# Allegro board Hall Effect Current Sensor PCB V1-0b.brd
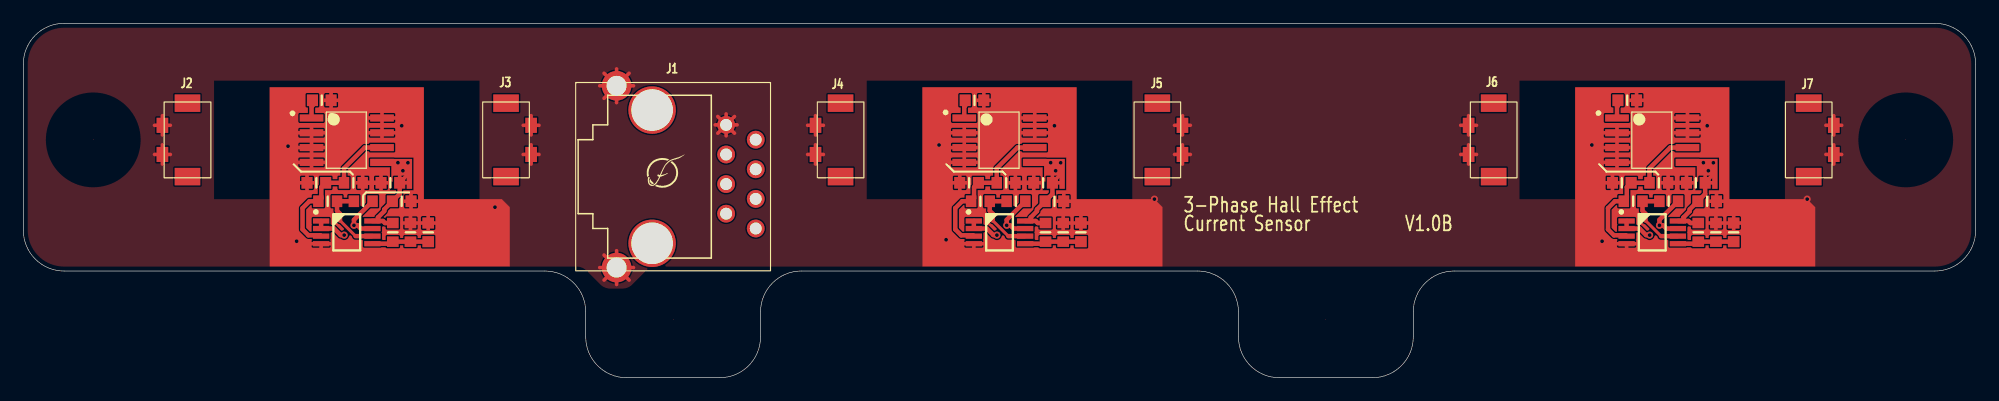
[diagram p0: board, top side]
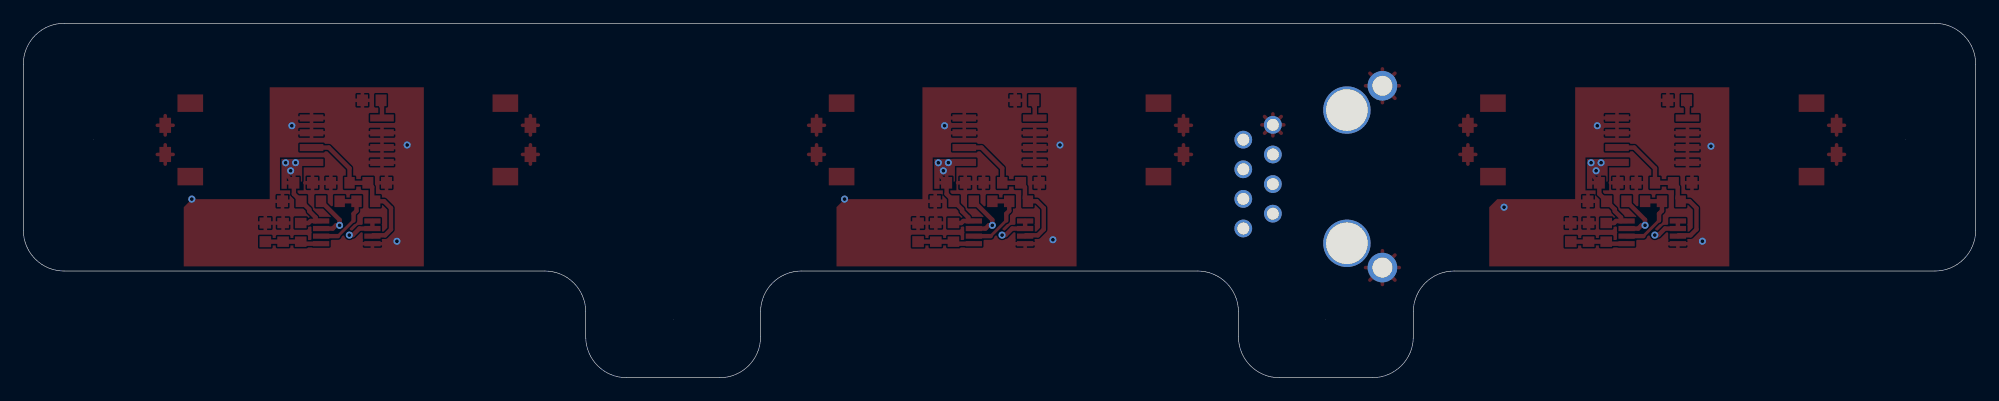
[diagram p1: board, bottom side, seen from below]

Outline 167.5 x 30.4 mm; copper layers: TOP, LAYER_2, LAYER_3, BOTTOM. Coordinates in mm from the lower left corner of the outline.
Outline path: 0,26.9 arc(1.03,29.37) 3.5,30.4 164,30.4 arc(166.47,29.37) 167.5,26.9 167.5,12.65 arc(166.47,10.18) 164,9.15 122.75,9.15 arc(120.28,8.12) 119.25,5.65 119.25,3.5 arc(118.22,1.03) 115.75,0 107.75,0 arc(105.28,1.03) 104.25,3.5 104.25,5.65 arc(103.22,8.12) 100.75,9.15 66.75,9.15 arc(64.28,8.12) 63.25,5.65 63.25,3.5 arc(62.22,1.03) 59.75,0 51.75,0 arc(49.28,1.03) 48.25,3.5 48.25,5.65 arc(47.22,8.12) 44.75,9.15 3.5,9.15 arc(1.03,10.18) 0,12.65 0,26.9

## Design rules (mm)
constraint set DEFAULT: min track width 0.127, pair gap 0.178
net group OUTPUT_A: nets OUTPUT_A_N OUTPUT_A_P
net group OUTPUT_B: nets OUTPUT_B_N OUTPUT_B_P
net group OUTPUT_C: nets OUTPUT_C_N OUTPUT_C_P

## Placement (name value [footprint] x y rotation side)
C1  0.047uF  [CAPC1608X90N]  25.61 23.8 0 top
C2  0.1uF  [CAPC1608X87N]  31.49 16.72 180 top
C3  10000pF  [CAPC1608X90N]  25.14 16.72 180 top
C4  0.047uF  [CAPC1608X90N]  81.61 23.8 0 top
C5  0.1uF  [CAPC1608X87N]  87.49 16.72 180 top
C6  10000pF  [CAPC1608X90N]  81.14 16.72 180 top
C7  0.047uF  [CAPC1608X90N]  137.61 23.8 0 top
C8  0.1uF  [CAPC1608X87N]  143.49 16.72 180 top
C9  10000pF  [CAPC1608X90N]  137.14 16.72 180 top
C10  0.1uF  [CAPC1608X87N]  34.74 12.47 90 top
C11  0.1uF  [CAPC1608X87N]  90.74 12.47 90 top
C12  0.1uF  [CAPC1608X87N]  146.74 12.47 90 top
CB19  0.1uF  [CAPC1608X87N]  32.46 15.14 0 top
CB20  0.1uF  [CAPC1608X87N]  88.46 15.14 0 top
CB21  0.1uF  [CAPC1608X87N]  144.46 15.14 0 top
J1  A-2014-2S-4-N-R  [RJ45_VERT_SHIELD_CON]  60.3 21.69 90 top
J2  CON2  [AVX_9155_MOBO_2PIN]  14.08 20.4 90 top
J3  CON2  [AVX_9155_MOBO_2PIN]  41.42 20.4 270 top
J4  CON2  [AVX_9155_MOBO_2PIN]  70.11 20.4 90 top
J5  CON2  [AVX_9155_MOBO_2PIN]  97.3 20.4 270 top
J6  CON2  [AVX_9155_MOBO_2PIN]  126.14 20.4 90 top
J7  CON2  [AVX_9155_MOBO_2PIN]  153.18 20.4 270 top
NOREF  -  []  100.73 15.82 0 top
NOREF#2  -  []  16.74 24.91 0 top
NOREF#3  -  []  53.48 16.3 0 top
NOREF#4  -  [unnamed#2]  55.75 5 0 top
NOREF#5  -  [unnamed#2]  111.75 5 0 top
NOREF#6  -  [unnamed#2]  6 20.4 0 top
NOREF#7  -  []  16.74 15.7 90 top
NOREF#8  -  [unnamed#2]  161.5 20.4 0 top
NOREF#9  -  []  0 19.77 0 top
NOREF#10  -  []  55.75 0 90 top
R1  10k  [RESC1608X55N]  28.31 16.72 180 top
R4  10k  [RESC1608X55N]  84.31 16.72 180 top
R6  10k  [RESC1608X55N]  140.31 16.72 180 top
R7  10k  [RESC1608X55N]  29.16 15.14 0 top
R8  10k  [RESC1608X55N]  26.11 15.14 0 top
R9  10k  [RESC1608X55N]  85.16 15.14 0 top
R10  10k  [RESC1608X55N]  82.11 15.14 0 top
R11  10k  [RESC1608X55N]  141.16 15.14 0 top
R12  10k  [RESC1608X55N]  138.11 15.14 0 top
R13  10k  [RESC1608X55N]  33.21 12.47 90 top
R14  10k  [RESC1608X55N]  31.7 12.47 270 top
R15  10k  [RESC1608X55N]  87.7 12.47 270 top
R16  10k  [RESC1608X55N]  89.21 12.47 90 top
R17  10k  [RESC1608X55N]  143.7 12.47 270 top
R18  10k  [RESC1608X55N]  145.21 12.47 90 top
U1  MLX91208LDC-CAH-000-TU  [SOIC_8]  24.73 22.28 0 top
U2  MLX91208LDC-CAH-000-TU  [SOIC_8]  80.73 22.28 0 top
U3  MLX91208LDC-CAH-000-TU  [SOIC_8]  136.73 22.28 0 top
U4  AD8616ARMZ-REEL  [MSOP8_0_65X4_40P_H1_10]  27.75 12.47 0 top
U5  AD8616ARMZ-REEL  [MSOP8_0_65X4_40P_H1_10]  83.75 12.47 0 top
U6  AD8616ARMZ-REEL  [MSOP8_0_65X4_40P_H1_10]  139.75 12.47 0 top

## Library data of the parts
C1-C12 CB19-CB21 = CAP
J1 = ModularJack8P8C-shielded
J2-J7 = CON2
R1 R4 R6 = RES_0
R7-R18 = R
U1-U3 = MLX91208
U4-U6 = OPAMP_2X_8P

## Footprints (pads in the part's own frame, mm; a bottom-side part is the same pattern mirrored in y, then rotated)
AVX_9155_MOBO_2PIN
  rect 1.5x2.2 smd: (-3.15,0) (3.15,0)
  rect 1.3x1 smd: 1(-1.25,2.15) 2(1.25,2.15)
CAPC1608X87N
  rect 0.95x1 smd: 1(-0.8,0) 2(0.8,0)
CAPC1608X90N
  rect 0.95x1 smd: 1(-0.8,0) 2(0.8,0)
MSOP8_0_65X4_40P_H1_10
  rect 1.4x0.45 smd: 1(-2.2,0.975) 2(-2.2,0.325) 3(-2.2,-0.325) 4(-2.2,-0.975) 5(2.2,-0.975) 6(2.2,-0.325) 7(2.2,0.325) 8(2.2,0.975)
RESC1608X55N
  rect 0.9x1 smd: 1(-0.8,0) 2(0.8,0)
RJ45_VERT_SHIELD_CON
  round 4.064 hole 3.556: (-10.16,6.35) (1.27,6.35)
  round 1.524 hole 1.016: 1(0,0) 2(-1.27,-2.54) 3(-2.54,0) 4(-3.81,-2.54) 5(-5.08,0) 6(-6.35,-2.54) 7(-7.62,0) 8(-8.89,-2.54)
  round 2.54 hole 1.702: S1(3.353,9.398) S2(-12.243,9.398)
SOIC_8
  rect 2.032x0.61 smd: 1(0,0) 2(0,-1.27) 3(0,-2.54) 4(0,-3.81) 5(6.045,-3.81) 6(6.045,-2.54) 7(6.045,-1.27) 8(6.045,0)
unnamed#2
  round 0.025 hole 4.496 unplated: (0,0)

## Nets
+2V5REF_A: C10.1 R13.1 R14.2 U4.5
+2V5REF_B: C11.1 R15.2 R16.1 U5.5
+2V5REF_C: C12.1 R17.2 R18.1 U6.5
+5V: C2.1 C5.1 C8.1 CB19.1 CB20.1 CB21.1 J1.2 R14.1 R15.1 R17.1 U1.5 U2.5 U3.5 U4.8 U5.8 U6.8
0: C1.2 C2.2 C3.2 C4.2 C5.2 C6.2 C7.2 C8.2 C9.2 C10.2 C11.2 C12.2 CB19.2 CB20.2 CB21.2 J1.1 J1.S1 J1.S2(SHIELD2) J2.1 J2.2 J3.1 J3.2 J4.1 J4.2 J5.1 J5.2 J6.1 J6.2 J7.1 J7.2 R1.1 R4.1 R6.1 R13.2 R16.2 R18.2 U1.2 U1.3(VSS) U1.4 U1.7 U1.8 U2.2 U2.3(VSS) U2.4 U2.7 U2.8 U3.2 U3.3(VSS) U3.4 U3.7 U3.8 U4.4 U5.4 U6.4
OUTPUT_A: C3.1 R1.2 R8.1 U1.6 U4.3
OUTPUT_A_N: J1.3 R7.2 U4.7(OUT2)
OUTPUT_A_P: J1.6 U4.1 U4.2
OUTPUT_B: C6.1 R4.2 R10.1 U2.6 U5.3
OUTPUT_B_N: J1.5 R9.2 U5.7(OUT2)
OUTPUT_B_P: J1.4 U5.1 U5.2
OUTPUT_C: C9.1 R6.2 R12.1 U3.6 U6.3
OUTPUT_C_N: J1.7 R11.2 U6.7(OUT2)
OUTPUT_C_P: J1.8 U6.1 U6.2
N4844729: C1.1 U1.1
N4845886: C4.1 U2.1
N4846468: C7.1 U3.1
N4848257: R7.1 R8.2 U4.6
N4851782: R9.1 R10.2 U5.6
N4852376: R11.1 R12.2 U6.6

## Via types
v1: diameter 0.61, hole 0.33, TOP to BOTTOM, 27 vias

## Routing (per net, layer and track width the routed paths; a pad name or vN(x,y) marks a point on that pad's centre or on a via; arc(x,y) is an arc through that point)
+2V5REF_A: length 4.9
  TOP w0.381: U4.5 31.53,11.49 R14.2 R13.1 C10.1
+2V5REF_B: length 4.9
  TOP w0.381: C11.1 R16.1 R15.2 87.53,11.49 U5.5
+2V5REF_C: length 4.9
  TOP w0.381: U6.5 143.53,11.49 R17.2 R18.1 C12.1
+5V: length 31.3
  TOP w0.305: C5.1 88.93,17.4 ; C5.1 88.94,16.72 ; C5.1 88.29,17.4 ; C2.1 32.29,17.4 ; C2.1 32.94,16.72 ; C2.1 32.93,17.4 ; C8.1 144.93,17.4 ; C8.1 144.29,17.4 ; C8.1 144.94,16.72
  TOP w0.381: R15.1 87.03,13.27 86.85,13.44 86.43,13.44 ; C5.1 88.29,15.76 CB20.1 86.96,14.44 86.96,14.28 86.43,13.74 86.43,13.44 ; 86.43,13.44 U5.8 ; 30.43,13.44 30.85,13.44 31.03,13.27 R14.1 ; 30.43,13.44 30.43,13.74 30.96,14.28 30.96,14.44 CB19.1 32.29,15.76 C2.1 ; 30.43,13.44 U4.8 ; 142.43,13.44 142.85,13.44 143.03,13.27 R17.1 ; 142.43,13.44 142.43,13.74 142.96,14.28 142.96,14.44 CB21.1 144.29,15.76 C8.1 ; 142.43,13.44 U6.8
  LAYER_2 w0.305: J1.2 63.78,20.42 ; J1.2 62.12,19.7 ; J1.2 62.84,21.36 ; J1.2 61.9,20.42 ; J1.2 63.55,21.13 ; J1.2 63.55,19.7 ; J1.2 62.12,21.13
  vias: v1(32.14,18.44) v1(32.57,17.75) v1(33,18.44) v1(88.14,18.44) v1(88.57,17.75) v1(89,18.44) v1(144.14,18.44) v1(144.57,17.75) v1(145,18.44)
0: length 199
  TOP w0.305: 137.55,11.09 U6.4 ; U6.4 138.43,11.49 ; U6.4 136.67,11.49 ; 30.77,22.28 30.77,22.76 ; 30.77,22.28 31.97,22.28 ; 30.77,22.28 29.58,22.28 ; 30.77,22.28 30.77,21.8 ; 145.26,14.46 CB21.2 ; CB21.2 145.26,15.81 ; CB21.2 145.92,15.14 ; CB21.2 144.61,15.14 ; 60.3,20.75 J1.1 ; J1.1 61.24,21.69 ; J1.1 59.58,20.97 ; J1.1 59.36,21.69 ; J1.1 61.01,20.97 ; J1.1 60.3,22.63 ; J1.1 59.58,22.4 ; J1.1 61.01,22.4 ; 98.77,21.65 J5.1 ; J5.1 99.45,20.82 ; J5.1 99.45,22.48 ; J5.1 100.12,21.65 ; R13.2 33.21,13.9 ; R13.2 32.54,13.27 ; R13.2 33.21,12.64 ; R13.2 33.89,13.27 ; 80.73,20.53 U2.2 ; U2.2 79.53,21.01 ; U2.2 81.92,21.01 ; U2.2 80.73,21.49 ; 123.99,20.82 J6.2 ; J6.2 124.67,21.65 ; J6.2 123.32,21.65 ; J6.2 123.99,22.48 ; J2.2 12.61,21.65 ; J2.2 11.93,20.82 ; J2.2 11.26,21.65 ; J2.2 11.93,22.48 ; 30.77,21.01 31.97,21.01 ; 30.77,21.01 30.77,21.49 ; 30.77,21.01 29.58,21.01 ; 30.77,21.01 30.77,20.53 ; 98.77,19.15 J5.2 ; J5.2 99.45,18.32 ; J5.2 99.45,19.98 ; J5.2 100.12,19.15 ; 25.55,11.09 U4.4 ; U4.4 24.67,11.49 ; U4.4 26.43,11.49 ; U5.4 82.43,11.49 ; U5.4 80.67,11.49 ; U5.4 81.55,11.09 ; U2.3 81.92,19.74 ; U2.3 80.73,19.26 ; U2.3 79.53,19.74 ; U2.3 80.73,20.22 ; 85.58,21.01 U2.7 ; U2.7 86.77,21.49 ; U2.7 87.97,21.01 ; U2.7 86.77,20.53 ; J3.1 43.57,22.48 ; J3.1 43.57,20.82 ; J3.1 44.24,21.65 ; J3.1 42.89,21.65 ; U3.2 137.92,21.01 ; U3.2 136.73,20.53 ; U3.2 136.73,21.49 ; U3.2 135.53,21.01 ; 79.69,16.72 C6.2 ; C6.2 80.34,16.04 ; C6.2 80.34,17.4 ; C6.2 80.99,16.72 ; 155.33,20.82 J7.1 ; J7.1 154.65,21.65 ; J7.1 156,21.65 ; J7.1 155.33,22.48 ; R16.2 89.21,13.9 ; R16.2 89.21,12.64 ; R16.2 89.89,13.27 ; R16.2 88.54,13.27 ; 80.73,17.99 U2.4 ; U2.4 79.53,18.47 ; U2.4 81.92,18.47 ; U2.4 80.73,18.95 ; C7.2 139.06,23.8 ; C7.2 137.75,23.8 ; C7.2 138.41,24.47 ; C7.2 138.41,23.12 ; 85.58,22.28 U2.8 ; U2.8 86.77,22.76 ; U2.8 86.77,21.8 ; U2.8 87.97,22.28 ; R18.2 145.89,13.27 ; R18.2 145.21,13.9 ; R18.2 144.54,13.27 ; R18.2 145.21,12.64 ; C12.2 147.41,13.27 ; C12.2 146.74,13.92 ; C12.2 146.06,13.27 ; C12.2 146.74,12.62 ; J1.S1 51.97,26.12 ; J1.S1 50.9,26.49 ; J1.S1 49.82,23.97 ; J1.S1 49.82,26.12 ; J1.S1 50.9,23.59 ; J1.S1 49.45,25.04 ; J1.S1 52.35,25.04 ; J1.S2 51.97,8.37 ; J1.S2 52.35,9.45 ; J1.S2 50.9,8 ; J1.S2 49.82,8.37 ; J1.S2 50.9,10.89 ; J1.S2 49.45,9.45 ; J1.S2 49.82,10.52 ; 43.57,18.32 J3.2 ; J3.2 44.24,19.15 ; J3.2 43.57,19.98 ; J3.2 42.89,19.15 ; 135.69,16.72 C9.2 ; C9.2 136.34,16.04 ; C9.2 136.34,17.4 ; C9.2 136.99,16.72 ; 82.41,23.12 C4.2 ; C4.2 81.75,23.8 ; C4.2 83.06,23.8 ; C4.2 82.41,24.47 ; 90.74,12.62 C11.2 ; C11.2 91.41,13.27 ; C11.2 90.06,13.27 ; C11.2 90.74,13.92 ; J6.1 123.99,19.98 ; J6.1 123.99,18.32 ; J6.1 123.32,19.15 ; J6.1 124.67,19.15 ; C8.2 142.69,17.4 ; C8.2 143.34,16.72 ; C8.2 142.69,16.04 ; 142.77,21.8 U3.8 ; U3.8 142.77,22.76 ; U3.8 143.97,22.28 ; U3.8 141.58,22.28 ; 84.49,16.72 R4.1 ; R4.1 85.11,17.4 ; R4.1 85.11,16.04 ; 24.73,19.26 U1.3 ; U1.3 25.92,19.74 ; U1.3 23.53,19.74 ; U1.3 24.73,20.22 ; C3.2 24.34,17.4 ; C3.2 24.34,16.04 ; C3.2 23.69,16.72 ; C3.2 24.99,16.72 ; 24.73,17.99 U1.4 ; U1.4 23.53,18.47 ; U1.4 24.73,18.95 ; U1.4 25.92,18.47 ; C10.2 35.41,13.27 ; C10.2 34.06,13.27 ; C10.2 34.74,13.92 ; C10.2 34.74,12.62 ; 67.29,19.15 J4.1 ; J4.1 67.96,19.98 ; J4.1 67.96,18.32 ; J4.1 68.64,19.15 ; 30.69,16.04 C2.2 ; C2.2 31.34,16.72 ; C2.2 30.69,17.4 ; 28.49,16.72 R1.1 ; R1.1 29.11,16.04 ; R1.1 29.11,17.4 ; 86.69,16.04 C5.2 ; C5.2 87.34,16.72 ; C5.2 86.69,17.4 ; U3.3 137.92,19.74 ; U3.3 136.73,19.26 ; U3.3 135.53,19.74 ; U3.3 136.73,20.22 ; J7.2 155.33,19.98 ; J7.2 156,19.15 ; J7.2 155.33,18.32 ; J7.2 154.65,19.15 ; 26.41,23.12 C1.2 ; C1.2 25.75,23.8 ; C1.2 27.06,23.8 ; C1.2 26.41,24.47 ; 67.96,20.82 J4.2 ; J4.2 68.64,21.65 ; J4.2 67.96,22.48 ; J4.2 67.29,21.65 ; U3.7 142.77,21.49 ; U3.7 142.77,20.53 ; U3.7 143.97,21.01 ; U3.7 141.58,21.01 ; J2.1 12.61,19.15 ; J2.1 11.26,19.15 ; J2.1 11.93,18.32 ; J2.1 11.93,19.98 ; R6.1 141.11,17.4 ; R6.1 141.11,16.04 ; R6.1 140.49,16.72 ; CB20.2 89.26,15.81 ; CB20.2 89.92,15.14 ; CB20.2 89.26,14.46 ; CB20.2 88.61,15.14 ; 32.61,15.14 CB19.2 ; CB19.2 33.26,15.81 ; CB19.2 33.92,15.14 ; CB19.2 33.26,14.46 ; 136.73,17.99 U3.4 ; U3.4 135.53,18.47 ; U3.4 137.92,18.47 ; U3.4 136.73,18.95 ; U1.2 25.92,21.01 ; U1.2 24.73,20.53 ; U1.2 23.53,21.01 ; U1.2 24.73,21.49
  TOP w0.381: R1.1 C2.2 ; R4.1 C5.2 ; R6.1 C8.2
  LAYER_3 w0.305: 49.82,26.12 J1.S1 ; J1.S1 50.9,26.49 ; J1.S1 52.35,25.04 ; J1.S1 49.45,25.04 ; J1.S1 50.9,23.59 ; J1.S1 49.82,23.97 ; J1.S1 51.97,26.12 ; J1.1 60.3,22.63 ; J1.1 61.01,22.4 ; J1.1 61.01,20.97 ; J1.1 59.36,21.69 ; J1.1 59.58,20.97 ; J1.1 61.24,21.69 ; J1.1 59.58,22.4 ; J1.1 60.3,20.75 ; 49.82,10.52 J1.S2 50.9,10.89
  vias: v1(22.71,19.86) v1(23.45,11.71) v1(32.46,21.61) v1(40.46,14.63) v1(78.56,19.96) v1(79.17,11.83) v1(88.46,21.61) v1(97.04,15.32) v1(134.57,19.96) v1(135.45,11.71) v1(144.46,21.61) v1(153.04,15.32)
OUTPUT_A: length 13.9
  TOP w0.381: U4.3 25.48,12.21 24.46,12.21 23.95,12.72 23.95,14.54 24.55,15.14 R8.1 25.57,15.39 25.57,16.35 C3.1 R1.2 27.51,17.97 29.29,19.74 30.77,19.74
OUTPUT_A_N: length 38.9
  TOP w0.381: U4.7 28.95,12.79 28.67,13.07 v1(28.37,13.07) 28.37,13.54 R7.2
  LAYER_2 w0.381: v1(28.37,13.07) 28.99,13.07 29.03,13.03 40.49,13.03 45.26,17.8 58.95,17.8 J1.3
OUTPUT_A_P: length 41
  TOP w0.381: U4.1 U4.2 26.66,12.79 27.22,12.23 v1(27.53,12.23)
  LAYER_2 w0.381: J1.6 59.95,15.34 58.04,17.24 45.49,17.24 40.72,12.47 28.64,12.47 28.63,12.45 27.75,12.45 v1(27.53,12.23)
OUTPUT_B: length 13.9
  TOP w0.381: U2.6 85.29,19.74 83.51,17.97 R4.2 C6.1 81.57,16.35 81.57,15.39 R10.1 80.55,15.14 79.95,14.54 79.95,12.72 80.46,12.21 81.48,12.21 U5.3
OUTPUT_B_N: length 32.4
  TOP w0.381: U5.7 84.95,12.79 84.67,13.07 v1(84.37,13.07) 84.37,13.54 R9.2
  LAYER_2 w0.381: J1.5 61.06,17.37 61.06,17.95 62.31,19.2 64.21,19.2 69.72,13.69 83.74,13.69 v1(84.37,13.07)
OUTPUT_B_P: length 26.2
  TOP w0.381: v1(83.53,12.23) 83.22,12.23 82.66,12.79 U5.2 U5.1
  LAYER_2 w0.381: J1.4 64.74,17.88 69.49,13.14 83.07,13.14 83.53,12.68 v1(83.53,12.23)
OUTPUT_C: length 13.9
  TOP w0.381: U3.6 141.29,19.74 139.51,17.97 R6.2 C9.1 137.57,16.35 137.57,15.39 R12.1 136.55,15.14 135.95,14.54 135.95,12.72 136.46,12.21 137.48,12.21 U6.3
OUTPUT_C_N: length 87.1
  TOP w0.381: U6.7 140.95,12.79 140.67,13.07 v1(140.37,13.07) 140.37,13.54 R11.2
  LAYER_2 w0.381: v1(140.37,13.07) 139.92,13.07 139.38,13.62 130.39,13.62 127.71,10.94 67.11,10.94 63.98,14.07 J1.7
OUTPUT_C_P: length 82.3
  TOP w0.381: v1(139.53,12.23) 139.22,12.23 138.66,12.79 U6.2 U6.1
  LAYER_2 w0.381: v1(139.53,12.23) 139.53,12.68 139.15,13.06 130.62,13.06 127.95,10.39 66.88,10.39 64.46,12.8 J1.8
N4844729: length 1.5
  TOP w0.381: C1.1 24.81,23.33 24.73,23.26 U1.1
N4845886: length 1.5
  TOP w0.381: U2.1 80.73,23.26 80.81,23.33 C4.1
N4846468: length 1.5
  TOP w0.381: U3.1 136.73,23.26 136.81,23.33 C7.1
N4848257: length 6.5
  TOP w0.254: 27.17,13.48 28.51,12.14
  TOP w0.381: 27.17,13.48 27.17,14.06 26.91,14.32 R8.2 R7.1 ; 28.51,12.14 U4.6
N4851782: length 6.5
  TOP w0.254: 83.17,13.48 84.51,12.14
  TOP w0.381: 83.17,13.48 83.17,14.06 82.91,14.32 R10.2 R9.1 ; 84.51,12.14 U5.6
N4852376: length 6.5
  TOP w0.254: 139.17,13.48 140.51,12.14
  TOP w0.381: 139.17,13.48 139.17,14.06 138.91,14.32 R12.2 R11.1 ; 140.51,12.14 U6.6

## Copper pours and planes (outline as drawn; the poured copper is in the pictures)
+5V on TOP (solid shape): 33.35,16.2 32.89,16.2 32.89,17.22 32.85,17.31 32.76,17.34 31.81,17.34 31.72,17.31 31.69,17.22 31.69,16.82 31.61,16.82 31.57,16.87 31.57,18.18 29.87,18.18 29.87,18.77 33.35,18.77
+5V on TOP (solid shape): 89.35,16.2 88.89,16.2 88.89,17.22 88.85,17.31 88.76,17.34 87.81,17.34 87.72,17.31 87.69,17.22 87.69,16.82 87.61,16.82 87.57,16.87 87.57,18.18 85.87,18.18 85.87,18.77 89.35,18.77
+5V on TOP (solid shape): 145.35,16.2 144.89,16.2 144.89,17.22 144.85,17.31 144.76,17.34 143.81,17.34 143.72,17.31 143.69,17.22 143.69,16.82 143.61,16.82 143.57,16.87 143.57,18.18 141.87,18.18 141.87,18.77 145.35,18.77
+5V on LAYER_2: 0.38,26.9 1.29,29.11 3.5,30.02 164,30.02 166.21,29.11 167.12,26.9 167.12,12.65 166.21,10.44 164,9.53 3.5,9.53 1.29,10.44 0.38,12.65 ; 6 cut-outs
(no net) on TOP: 141.87,18.77 145.35,18.77 145.35,16.2 143.57,16.2 143.57,18.18 141.87,18.18
(no net) on TOP: 21.14,24.91 34.36,24.91 34.36,15.32 41.04,15.32 41.73,14.63 41.73,9.55 21.14,9.55 ; 1 cut-out
(no net) on TOP: 85.87,18.77 89.35,18.77 89.35,16.2 87.57,16.2 87.57,18.18 85.87,18.18
(no net) on TOP: 29.87,18.77 33.35,18.77 33.35,16.2 31.57,16.2 31.57,18.18 29.87,18.18
(no net) on TOP: 77.14,24.91 90.36,24.91 90.36,15.32 97.04,15.32 97.73,14.63 97.73,9.55 77.14,9.55 ; 1 cut-out
(no net) on TOP: 133.14,24.91 146.36,24.91 146.36,15.32 153.04,15.32 153.73,14.63 153.73,9.55 133.14,9.55 ; 1 cut-out
0 on TOP (solid shape): outline of 1105 points within 77.14,9.55 97.73,24.91
0 on TOP (solid shape): outline of 1106 points within 21.14,9.55 41.73,24.91
0 on TOP (solid shape): outline of 1105 points within 133.14,9.55 153.73,24.91
0 on TOP: 0.38,26.9 1.29,29.11 3.5,30.02 164,30.02 166.21,29.11 167.12,26.9 167.12,12.65 166.21,10.44 164,9.53 54.29,9.53 53.82,9.44 53.42,9.17 52.25,8 51.86,7.74 51.39,7.64 50.37,7.64 49.9,7.74 49.5,8 48.33,9.17 47.94,9.44 47.47,9.53 3.5,9.53 1.29,10.44 0.38,12.65 ; 8 cut-outs
0 on LAYER_3: 0.38,26.9 1.29,29.11 3.5,30.02 164,30.02 166.21,29.11 167.12,26.9 167.12,12.65 166.21,10.44 164,9.53 3.5,9.53 1.29,10.44 0.38,12.65 ; 5 cut-outs

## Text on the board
User.Comments: CR_MELEXIS-RESISTOR-DIV_1 | CR_MELEXIS_1
Ref Des/Silkscreen Top: 3-Phase Hall Effect | Current Sensor | V1.0B
XSECTION_CHART: *  SURFACE - 0 MIL | *  DIELECTRIC - 0.6 MIL | L1 TOP CONDUCTOR - 1.8 MIL | *  DIELECTRIC - 7.94 MIL | L2 LAYER_2 CONDUCTOR - 1.2 MIL | *  DIELECTRIC - 39 MIL | L3 LAYER_3 CONDUCTOR - 1.2 MIL | L4 BOTTOM CONDUCTOR - 1.8 MIL | DESIGN CROSS SECTION CHART | ___________________________ | TOTAL THICKNESS 62.08 MIL | 1-4 | FIGURE | FINISHED_SIZE | 13.0 | 40.0 | 67.0 | 140.0 | 177.0 | DRILL CHART: TOP to BOTTOM | ALL UNITS ARE IN MILS | PLATED | NON-PLATED | QTY | 27 | 8 | 2 | 4
